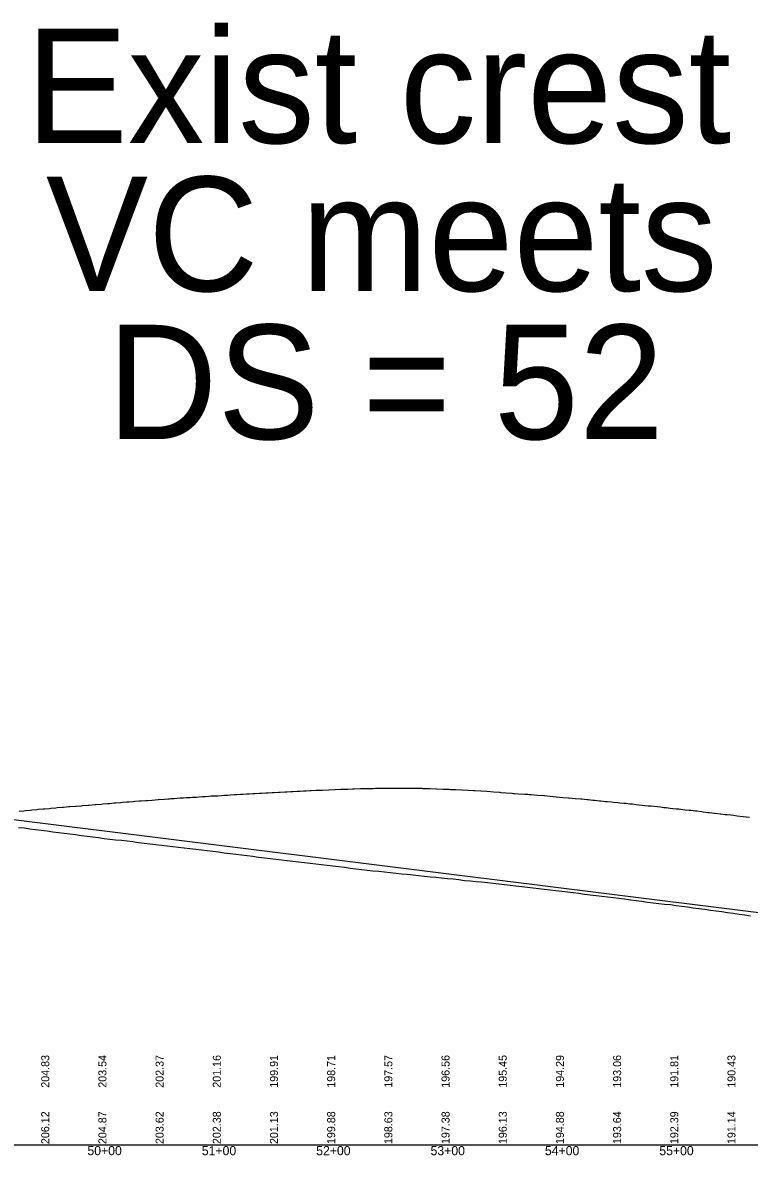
# Model space of a CAD drawing. Extents: x 1876258 to 1932803, y 754739 to 837911.
# Drawn here: x 1881589 to 1882224, y 820541 to 821531 of the extents above; entities that cross this region are included whole.
import ezdxf

# ---------------------------------------------------------------- set-up
doc = ezdxf.new("R2010")
doc.units = 0
for name, color, linetype in [('RD_DDB_Profile_EX', 7, 'Continuous'), ('RD_DDB_Profile_PR', 7, 'Continuous'), ('RD_DDB_StaTX', 7, 'Continuous'), ('RD_DDB_StripGrade', 7, 'Continuous'), ('RD_GPK_Profile_Cell', 7, 'Continuous'), ('RD_Sketch1', 7, 'Continuous')]:
    doc.layers.add(name, color=color, linetype=linetype)

msp = doc.modelspace()

# ---------------------------------------------------------------- linework, layer by layer
at = {"layer": 'RD_DDB_Profile_EX'}
for points in [[(1881585.15, 820827.81), (1881590.15, 820827.26), (1881595.15, 820826.62), (1881600.15, 820825.84), (1881605.15, 820825.25), (1881610.15, 820824.65), (1881615.15, 820824.01), (1881620.15, 820823.34), (1881625.15, 820822.71), (1881630.15, 820822.08), (1881635.15, 820821.43), (1881640.15, 820820.79), (1881645.15, 820820.14), (1881650.15, 820819.48), (1881655.15, 820818.8), (1881660.15, 820818.13), (1881665.15, 820817.58), (1881670.15, 820817.02), (1881675.15, 820816.46), (1881680.15, 820815.88), (1881685.15, 820815.29), (1881690.15, 820814.66), (1881695.15, 820814.02), (1881700.15, 820813.44), (1881705.15, 820812.91), (1881710.15, 820812.32), (1881715.15, 820811.69), (1881720.15, 820811.08), (1881725.15, 820810.5), (1881730.15, 820809.92), (1881735.15, 820809.36), (1881740.15, 820808.8), (1881745.15, 820808.2), (1881750.15, 820807.57), (1881755.15, 820806.94), (1881760.15, 820806.31), (1881765.15, 820805.67), (1881770.15, 820805.08), (1881775.15, 820804.48), (1881780.15, 820803.83), (1881785.15, 820803.17), (1881790.15, 820802.49), (1881795.15, 820801.79), (1881800.15, 820801.21), (1881805.15, 820800.67), (1881810.15, 820800.05), (1881815.15, 820799.36), (1881820.15, 820798.74), (1881825.15, 820798.17), (1881830.15, 820797.59), (1881835.15, 820797.03), (1881840.15, 820796.44), (1881845.15, 820795.84), (1881850.15, 820795.24), (1881855.15, 820794.63), (1881860.15, 820794.02), (1881865.15, 820793.45), (1881870.15, 820792.87), (1881875.15, 820792.24), (1881880.15, 820791.6), (1881885.15, 820790.99), (1881890.15, 820790.37)], [(1881890.15, 820790.37), (1881895.15, 820789.85), (1881900.15, 820789.36), (1881905.15, 820788.84), (1881910.15, 820788.29), (1881915.15, 820787.78), (1881920.15, 820787.3), (1881925.15, 820786.8), (1881930.15, 820786.29), (1881935.15, 820785.76), (1881940.15, 820785.22), (1881945.15, 820784.68), (1881950.15, 820784.21), (1881955.15, 820783.73), (1881960.15, 820783.22), (1881965.15, 820782.7), (1881970.15, 820782.09), (1881975.15, 820781.47), (1881980.15, 820780.93), (1881985.15, 820780.47), (1881990.15, 820780.03), (1881995.15, 820779.48), (1882000.15, 820778.87), (1882005.15, 820778.28), (1882010.15, 820777.71), (1882015.15, 820777.13), (1882020.15, 820776.56), (1882025.15, 820776), (1882030.15, 820775.46), (1882035.15, 820774.91), (1882040.15, 820774.33), (1882045.15, 820773.74), (1882050.15, 820773.13), (1882055.15, 820772.51), (1882060.15, 820771.92), (1882065.15, 820771.36), (1882070.15, 820770.78), (1882075.15, 820770.14), (1882080.15, 820769.51), (1882085.15, 820768.88), (1882090.15, 820768.26), (1882095.15, 820767.64), (1882100.15, 820767.04), (1882105.15, 820766.42), (1882110.15, 820765.8), (1882115.15, 820765.17), (1882120.15, 820764.53), (1882125.15, 820763.88), (1882130.15, 820763.19), (1882135.15, 820762.53), (1882140.15, 820761.9), (1882145.15, 820761.29), (1882150.15, 820760.77), (1882155.15, 820760.22), (1882160.15, 820759.55), (1882165.15, 820758.87), (1882170.15, 820758.17), (1882175.15, 820757.49), (1882180.15, 820756.81), (1882185.15, 820756.13), (1882190.15, 820755.45), (1882195.15, 820754.76), (1882200.15, 820754.1), (1882205.15, 820753.45), (1882210.15, 820752.74), (1882215.15, 820751.97), (1882220.15, 820751.23), (1882225.15, 820750.53)]]:
    msp.add_lwpolyline(points, dxfattribs=at)
at = {"layer": 'RD_DDB_Profile_PR'}
msp.add_line((1881558.08, 820837.6), (1882275.08, 820748.07), dxfattribs=at)
at = {"layer": 'RD_GPK_Profile_Cell'}
msp.add_line((1878363.08, 820550.13), (1884763.08, 820550.13), dxfattribs=at)
at = {"layer": 'RD_Sketch1'}
msp.add_lwpolyline([(1881585.92, 820842.05), (1881589.88, 820842.39), (1881591.43, 820842.55), (1881595.37, 820842.96), (1881596.96, 820843.1), (1881601.17, 820843.5), (1881602.51, 820843.59), (1881606.81, 820843.9), (1881608, 820844.02), (1881612.38, 820844.43), (1881613.53, 820844.54), (1881617.99, 820844.96), (1881619.06, 820845.06), (1881623.76, 820845.49), (1881624.57, 820845.57), (1881629.16, 820846.01), (1881630.14, 820846.07), (1881634.78, 820846.35), (1881635.65, 820846.41), (1881640.29, 820846.76), (1881641.16, 820846.83), (1881646.05, 820847.24), (1881646.69, 820847.29), (1881652.21, 820847.73), (1881653.12, 820847.8), (1881657.73, 820848.19), (1881658.97, 820848.3), (1881663.25, 820848.66), (1881664.65, 820848.78), (1881668.77, 820849.13), (1881670.15, 820849.25), (1881674.31, 820849.56), (1881676.01, 820849.69), (1881679.82, 820850), (1881681.63, 820850.15), (1881685.34, 820850.47), (1881687.02, 820850.62), (1881690.89, 820850.88), (1881692.52, 820850.99), (1881696.4, 820851.28), (1881698.24, 820851.42), (1881701.92, 820851.69), (1881702.08, 820851.71), (1881707.45, 820852.12), (1881707.55, 820852.13), (1881712.87, 820852.48), (1881712.98, 820852.49), (1881715.94, 820852.68), (1881717.31, 820852.88), (1881718.5, 820852.96), (1881721.39, 820853.15), (1881724.02, 820853.34), (1881726.57, 820853.52), (1881729.57, 820853.68), (1881731.97, 820853.81), (1881735.08, 820854), (1881737.24, 820854.13), (1881740.6, 820854.34), (1881742.79, 820854.48), (1881746.12, 820854.7), (1881748.34, 820854.84), (1881751.64, 820855.07), (1881753.79, 820855.22), (1881757.19, 820855.39), (1881759.43, 820855.5), (1881762.7, 820855.69), (1881765.25, 820855.83), (1881768.21, 820856.03), (1881770.46, 820856.19), (1881773.74, 820856.4), (1881776.12, 820856.55), (1881779.28, 820856.7), (1881781.48, 820856.81), (1881784.78, 820857.04), (1881787.01, 820857.19), (1881790.31, 820857.4), (1881792.19, 820857.52), (1881795.85, 820857.71), (1881797.79, 820857.8), (1881801.38, 820857.96), (1881803.33, 820858.04), (1881806.9, 820858.21), (1881808.55, 820858.29), (1881812.42, 820858.5), (1881813.97, 820858.58), (1881817.94, 820858.8), (1881819.84, 820858.9), (1881823.46, 820859.09), (1881825.03, 820859.17), (1881828.99, 820859.37), (1881831.41, 820859.49), (1881834.52, 820859.63), (1881836.67, 820859.73), (1881840.04, 820859.89), (1881840.98, 820859.94), (1881845.54, 820860.23), (1881845.73, 820860.25), (1881850.9, 820860.45), (1881851.09, 820860.45), (1881856.47, 820860.68), (1881856.62, 820860.69), (1881861.83, 820860.91), (1881862.14, 820860.92), (1881866.93, 820861.12), (1881867.69, 820861.14), (1881872.57, 820861.25), (1881873.21, 820861.26), (1881877.64, 820861.36), (1881878.7, 820861.41), (1881884.23, 820861.66), (1881886.41, 820861.77), (1881886.56, 820861.77), (1881886.7, 820861.78), (1881886.8, 820861.78), (1881889.79, 820861.83), (1881890.24, 820861.84), (1881895.31, 820861.92), (1881897.47, 820861.96), (1881898.26, 820861.97), (1881900.84, 820862), (1881906.37, 820862.05), (1881908.55, 820862.07), (1881911.43, 820862.1), (1881911.65, 820862.1), (1881911.89, 820862.1), (1881917.42, 820862.15), (1881921.36, 820862.18), (1881921.77, 820862.18), (1881922.97, 820862.16), (1881928.49, 820862.09), (1881934.01, 820862.01), (1881937.8, 820861.95), (1881938.73, 820861.92), (1881939.56, 820861.9), (1881945.08, 820861.72), (1881950.27, 820861.56), (1881950.58, 820861.54), (1881950.62, 820861.54), (1881956.14, 820861.31), (1881961.66, 820861.08), (1881963.02, 820861.02), (1881963.26, 820861.01), (1881967.19, 820860.83), (1881972.72, 820860.58), (1881978.24, 820860.32), (1881983, 820860.1), (1881983.15, 820860.09), (1881983.79, 820860.05), (1881989.31, 820859.68), (1881994.54, 820859.33), (1881994.73, 820859.31), (1881994.84, 820859.3), (1882000.37, 820858.89), (1882005.89, 820858.47), (1882005.94, 820858.47), (1882006.62, 820858.42), (1882011.42, 820858.05), (1882016.94, 820857.62), (1882017.86, 820857.55), (1882018.94, 820857.47), (1882022.45, 820857.24), (1882027.98, 820856.86), (1882030.41, 820856.69), (1882031.58, 820856.6), (1882033.51, 820856.45), (1882039.03, 820856.03), (1882044.56, 820855.6), (1882045.05, 820855.56), (1882050.11, 820855.06), (1882055.39, 820854.53), (1882055.51, 820854.51), (1882055.61, 820854.5), (1882055.61, 820854.5), (1882061.14, 820854.03), (1882066.2, 820853.6), (1882066.66, 820853.56), (1882071.79, 820853.12), (1882072.18, 820853.09), (1882076.86, 820852.7), (1882077.73, 820852.61), (1882082.26, 820852.13), (1882083.26, 820852.02), (1882087.39, 820851.55), (1882088.76, 820851.43), (1882093.04, 820851.04), (1882094.28, 820850.93), (1882098.35, 820850.55), (1882099.81, 820850.4), (1882103.59, 820850.04), (1882105.33, 820849.88), (1882109.07, 820849.55), (1882110.86, 820849.37), (1882114.58, 820849.01), (1882116.39, 820848.83), (1882119.69, 820848.49), (1882121.93, 820848.23), (1882125.1, 820847.86), (1882127.45, 820847.59), (1882130.4, 820847.25), (1882132.94, 820847.02), (1882135.85, 820846.75), (1882138.48, 820846.5), (1882141.06, 820846.25), (1882144.02, 820845.9), (1882146.43, 820845.61), (1882149.54, 820845.26), (1882151.59, 820845.03), (1882155.06, 820844.66), (1882157.18, 820844.43), (1882160.58, 820844.08), (1882162.47, 820843.88), (1882166.12, 820843.45), (1882167.78, 820843.26), (1882171.62, 820842.87), (1882173.08, 820842.72), (1882177.16, 820842.25), (1882178.38, 820842.11), (1882182.69, 820841.57), (1882183.9, 820841.43), (1882188.21, 820840.93), (1882189.04, 820840.84), (1882193.73, 820840.31), (1882194.23, 820840.26), (1882198.68, 820839.71), (1882199.27, 820839.63), (1882202.94, 820839.17), (1882204.77, 820838.97), (1882207.94, 820838.62), (1882210.32, 820838.32), (1882213.69, 820837.88), (1882215.83, 820837.62), (1882218.75, 820837.27), (1882221.33, 820837), (1882224.33, 820836.68)], dxfattribs=at)
msp.add_lwpolyline([(1881585.92, 820842.05), (1881589.88, 820842.39), (1881591.43, 820842.55), (1881595.37, 820842.96), (1881596.96, 820843.1), (1881601.17, 820843.5), (1881602.51, 820843.59), (1881606.81, 820843.9), (1881608, 820844.02), (1881612.38, 820844.43), (1881613.53, 820844.54), (1881617.99, 820844.96), (1881619.06, 820845.06), (1881623.76, 820845.49), (1881624.57, 820845.57), (1881629.16, 820846.01), (1881630.14, 820846.07), (1881634.78, 820846.35), (1881635.65, 820846.41), (1881640.29, 820846.76), (1881641.16, 820846.83), (1881646.05, 820847.24), (1881646.69, 820847.29), (1881652.21, 820847.73), (1881653.12, 820847.8), (1881657.73, 820848.19), (1881658.97, 820848.3), (1881663.25, 820848.66), (1881664.65, 820848.78), (1881668.77, 820849.13), (1881670.15, 820849.25), (1881674.31, 820849.56), (1881676.01, 820849.69), (1881679.82, 820850), (1881681.63, 820850.15), (1881685.34, 820850.47), (1881687.02, 820850.62), (1881690.89, 820850.88), (1881692.52, 820850.99), (1881696.4, 820851.28), (1881698.24, 820851.42), (1881701.92, 820851.69), (1881702.08, 820851.71), (1881707.45, 820852.12), (1881707.55, 820852.13), (1881712.87, 820852.48), (1881712.98, 820852.49), (1881715.94, 820852.68), (1881717.31, 820852.88), (1881718.5, 820852.96), (1881721.39, 820853.15), (1881724.02, 820853.34), (1881726.57, 820853.52), (1881729.57, 820853.68), (1881731.97, 820853.81), (1881735.08, 820854), (1881737.24, 820854.13), (1881740.6, 820854.34), (1881742.79, 820854.48), (1881746.12, 820854.7), (1881748.34, 820854.84), (1881751.64, 820855.07), (1881753.79, 820855.22), (1881757.19, 820855.39), (1881759.43, 820855.5), (1881762.7, 820855.69), (1881765.25, 820855.83), (1881768.21, 820856.03), (1881770.46, 820856.19), (1881773.74, 820856.4), (1881776.12, 820856.55), (1881779.28, 820856.7), (1881781.48, 820856.81), (1881784.78, 820857.04), (1881787.01, 820857.19), (1881790.31, 820857.4), (1881792.19, 820857.52), (1881795.85, 820857.71), (1881797.79, 820857.8), (1881801.38, 820857.96), (1881803.33, 820858.04), (1881806.9, 820858.21), (1881808.55, 820858.29), (1881812.42, 820858.5), (1881813.97, 820858.58), (1881817.94, 820858.8), (1881819.84, 820858.9), (1881823.46, 820859.09), (1881825.03, 820859.17), (1881828.99, 820859.37), (1881831.41, 820859.49), (1881834.52, 820859.63), (1881836.67, 820859.73), (1881840.04, 820859.89), (1881840.98, 820859.94), (1881845.54, 820860.23), (1881845.73, 820860.25), (1881850.9, 820860.45), (1881851.09, 820860.45), (1881856.47, 820860.68), (1881856.62, 820860.69), (1881861.83, 820860.91), (1881862.14, 820860.92), (1881866.93, 820861.12), (1881867.69, 820861.14), (1881872.57, 820861.25), (1881873.21, 820861.26), (1881877.64, 820861.36), (1881878.7, 820861.41), (1881884.23, 820861.66), (1881886.41, 820861.77), (1881886.56, 820861.77), (1881886.7, 820861.78), (1881886.8, 820861.78), (1881889.79, 820861.83), (1881890.24, 820861.84), (1881895.31, 820861.92), (1881897.47, 820861.96), (1881898.26, 820861.97), (1881900.84, 820862), (1881906.37, 820862.05), (1881908.55, 820862.07), (1881911.43, 820862.1), (1881911.65, 820862.1), (1881911.89, 820862.1), (1881917.42, 820862.15), (1881921.36, 820862.18), (1881921.77, 820862.18), (1881922.97, 820862.16), (1881928.49, 820862.09), (1881934.01, 820862.01), (1881937.8, 820861.95), (1881938.73, 820861.92), (1881939.56, 820861.9), (1881945.08, 820861.72), (1881950.27, 820861.56), (1881950.58, 820861.54), (1881950.62, 820861.54), (1881956.14, 820861.31), (1881961.66, 820861.08), (1881963.02, 820861.02), (1881963.26, 820861.01), (1881967.19, 820860.83), (1881972.72, 820860.58), (1881978.24, 820860.32), (1881983, 820860.1), (1881983.15, 820860.09), (1881983.79, 820860.05), (1881989.31, 820859.68), (1881994.54, 820859.33), (1881994.73, 820859.31), (1881994.84, 820859.3), (1882000.37, 820858.89), (1882005.89, 820858.47), (1882005.94, 820858.47), (1882006.62, 820858.42), (1882011.42, 820858.05), (1882016.94, 820857.62), (1882017.86, 820857.55), (1882018.94, 820857.47), (1882022.45, 820857.24), (1882027.98, 820856.86), (1882030.41, 820856.69), (1882031.58, 820856.6), (1882033.51, 820856.45), (1882039.03, 820856.03), (1882044.56, 820855.6), (1882045.05, 820855.56), (1882050.11, 820855.06), (1882055.39, 820854.53), (1882055.51, 820854.51), (1882055.61, 820854.5), (1882055.61, 820854.5), (1882061.14, 820854.03), (1882066.2, 820853.6), (1882066.66, 820853.56), (1882071.79, 820853.12), (1882072.18, 820853.09), (1882076.86, 820852.7), (1882077.73, 820852.61), (1882082.26, 820852.13), (1882083.26, 820852.02), (1882087.39, 820851.55), (1882088.76, 820851.43), (1882093.04, 820851.04), (1882094.28, 820850.93), (1882098.35, 820850.55), (1882099.81, 820850.4), (1882103.59, 820850.04), (1882105.33, 820849.88), (1882109.07, 820849.55), (1882110.86, 820849.37), (1882114.58, 820849.01), (1882116.39, 820848.83), (1882119.69, 820848.49), (1882121.93, 820848.23), (1882125.1, 820847.86), (1882127.45, 820847.59), (1882130.4, 820847.25), (1882132.94, 820847.02), (1882135.85, 820846.75), (1882138.48, 820846.5), (1882141.06, 820846.25), (1882144.02, 820845.9), (1882146.43, 820845.61), (1882149.54, 820845.26), (1882151.59, 820845.03), (1882155.06, 820844.66), (1882157.18, 820844.43), (1882160.58, 820844.08), (1882162.47, 820843.88), (1882166.12, 820843.45), (1882167.78, 820843.26), (1882171.62, 820842.87), (1882173.08, 820842.72), (1882177.16, 820842.25), (1882178.38, 820842.11), (1882182.69, 820841.57), (1882183.9, 820841.43), (1882188.21, 820840.93), (1882189.04, 820840.84), (1882193.73, 820840.31), (1882194.23, 820840.26), (1882198.68, 820839.71), (1882199.27, 820839.63), (1882202.94, 820839.17), (1882204.77, 820838.97), (1882207.94, 820838.62), (1882210.32, 820838.32), (1882213.69, 820837.88), (1882215.83, 820837.62), (1882218.75, 820837.27), (1882221.33, 820837), (1882224.33, 820836.68)], dxfattribs=at)
msp.add_lwpolyline([(1881585.92, 820842.05), (1881589.88, 820842.39), (1881591.43, 820842.55), (1881595.37, 820842.96), (1881596.96, 820843.1), (1881601.17, 820843.5), (1881602.51, 820843.59), (1881606.81, 820843.9), (1881608, 820844.02), (1881612.38, 820844.43), (1881613.53, 820844.54), (1881617.99, 820844.96), (1881619.06, 820845.06), (1881623.76, 820845.49), (1881624.57, 820845.57), (1881629.16, 820846.01), (1881630.14, 820846.07), (1881634.78, 820846.35), (1881635.65, 820846.41), (1881640.29, 820846.76), (1881641.16, 820846.83), (1881646.05, 820847.24), (1881646.69, 820847.29), (1881652.21, 820847.73), (1881653.12, 820847.8), (1881657.73, 820848.19), (1881658.97, 820848.3), (1881663.25, 820848.66), (1881664.65, 820848.78), (1881668.77, 820849.13), (1881670.15, 820849.25), (1881674.31, 820849.56), (1881676.01, 820849.69), (1881679.82, 820850), (1881681.63, 820850.15), (1881685.34, 820850.47), (1881687.02, 820850.62), (1881690.89, 820850.88), (1881692.52, 820850.99), (1881696.4, 820851.28), (1881698.24, 820851.42), (1881701.92, 820851.69), (1881702.08, 820851.71), (1881707.45, 820852.12), (1881707.55, 820852.13), (1881712.87, 820852.48), (1881712.98, 820852.49), (1881715.94, 820852.68), (1881717.31, 820852.88), (1881718.5, 820852.96), (1881721.39, 820853.15), (1881724.02, 820853.34), (1881726.57, 820853.52), (1881729.57, 820853.68), (1881731.97, 820853.81), (1881735.08, 820854), (1881737.24, 820854.13), (1881740.6, 820854.34), (1881742.79, 820854.48), (1881746.12, 820854.7), (1881748.34, 820854.84), (1881751.64, 820855.07), (1881753.79, 820855.22), (1881757.19, 820855.39), (1881759.43, 820855.5), (1881762.7, 820855.69), (1881765.25, 820855.83), (1881768.21, 820856.03), (1881770.46, 820856.19), (1881773.74, 820856.4), (1881776.12, 820856.55), (1881779.28, 820856.7), (1881781.48, 820856.81), (1881784.78, 820857.04), (1881787.01, 820857.19), (1881790.31, 820857.4), (1881792.19, 820857.52), (1881795.85, 820857.71), (1881797.79, 820857.8), (1881801.38, 820857.96), (1881803.33, 820858.04), (1881806.9, 820858.21), (1881808.55, 820858.29), (1881812.42, 820858.5), (1881813.97, 820858.58), (1881817.94, 820858.8), (1881819.84, 820858.9), (1881823.46, 820859.09), (1881825.03, 820859.17), (1881828.99, 820859.37), (1881831.41, 820859.49), (1881834.52, 820859.63), (1881836.67, 820859.73), (1881840.04, 820859.89), (1881840.98, 820859.94), (1881845.54, 820860.23), (1881845.73, 820860.25), (1881850.9, 820860.45), (1881851.09, 820860.45), (1881856.47, 820860.68), (1881856.62, 820860.69), (1881861.83, 820860.91), (1881862.14, 820860.92), (1881866.93, 820861.12), (1881867.69, 820861.14), (1881872.57, 820861.25), (1881873.21, 820861.26), (1881877.64, 820861.36), (1881878.7, 820861.41), (1881884.23, 820861.66), (1881886.41, 820861.77), (1881886.56, 820861.77), (1881886.7, 820861.78), (1881886.8, 820861.78), (1881889.79, 820861.83), (1881890.24, 820861.84), (1881895.31, 820861.92), (1881897.47, 820861.96), (1881898.26, 820861.97), (1881900.84, 820862), (1881906.37, 820862.05), (1881908.55, 820862.07), (1881911.43, 820862.1), (1881911.65, 820862.1), (1881911.89, 820862.1), (1881917.42, 820862.15), (1881921.36, 820862.18), (1881921.77, 820862.18), (1881922.97, 820862.16), (1881928.49, 820862.09), (1881934.01, 820862.01), (1881937.8, 820861.95), (1881938.73, 820861.92), (1881939.56, 820861.9), (1881945.08, 820861.72), (1881950.27, 820861.56), (1881950.58, 820861.54), (1881950.62, 820861.54), (1881956.14, 820861.31), (1881961.66, 820861.08), (1881963.02, 820861.02), (1881963.26, 820861.01), (1881967.19, 820860.83), (1881972.72, 820860.58), (1881978.24, 820860.32), (1881983, 820860.1), (1881983.15, 820860.09), (1881983.79, 820860.05), (1881989.31, 820859.68), (1881994.54, 820859.33), (1881994.73, 820859.31), (1881994.84, 820859.3), (1882000.37, 820858.89), (1882005.89, 820858.47), (1882005.94, 820858.47), (1882006.62, 820858.42), (1882011.42, 820858.05), (1882016.94, 820857.62), (1882017.86, 820857.55), (1882018.94, 820857.47), (1882022.45, 820857.24), (1882027.98, 820856.86), (1882030.41, 820856.69), (1882031.58, 820856.6), (1882033.51, 820856.45), (1882039.03, 820856.03), (1882044.56, 820855.6), (1882045.05, 820855.56), (1882050.11, 820855.06), (1882055.39, 820854.53), (1882055.51, 820854.51), (1882055.61, 820854.5), (1882055.61, 820854.5), (1882061.14, 820854.03), (1882066.2, 820853.6), (1882066.66, 820853.56), (1882071.79, 820853.12), (1882072.18, 820853.09), (1882076.86, 820852.7), (1882077.73, 820852.61), (1882082.26, 820852.13), (1882083.26, 820852.02), (1882087.39, 820851.55), (1882088.76, 820851.43), (1882093.04, 820851.04), (1882094.28, 820850.93), (1882098.35, 820850.55), (1882099.81, 820850.4), (1882103.59, 820850.04), (1882105.33, 820849.88), (1882109.07, 820849.55), (1882110.86, 820849.37), (1882114.58, 820849.01), (1882116.39, 820848.83), (1882119.69, 820848.49), (1882121.93, 820848.23), (1882125.1, 820847.86), (1882127.45, 820847.59), (1882130.4, 820847.25), (1882132.94, 820847.02), (1882135.85, 820846.75), (1882138.48, 820846.5), (1882141.06, 820846.25), (1882144.02, 820845.9), (1882146.43, 820845.61), (1882149.54, 820845.26), (1882151.59, 820845.03), (1882155.06, 820844.66), (1882157.18, 820844.43), (1882160.58, 820844.08), (1882162.47, 820843.88), (1882166.12, 820843.45), (1882167.78, 820843.26), (1882171.62, 820842.87), (1882173.08, 820842.72), (1882177.16, 820842.25), (1882178.38, 820842.11), (1882182.69, 820841.57), (1882183.9, 820841.43), (1882188.21, 820840.93), (1882189.04, 820840.84), (1882193.73, 820840.31), (1882194.23, 820840.26), (1882198.68, 820839.71), (1882199.27, 820839.63), (1882202.94, 820839.17), (1882204.77, 820838.97), (1882207.94, 820838.62), (1882210.32, 820838.32), (1882213.69, 820837.88), (1882215.83, 820837.62), (1882218.75, 820837.27), (1882221.33, 820837), (1882224.33, 820836.68)], dxfattribs=at)

# ---------------------------------------------------------------- texts
at = {"layer": 'RD_DDB_StaTX'}
for s, p in [('50+00', (1881645.49, 820541.13)), ('51+00', (1881745.49, 820541.13)), ('52+00', (1881845.49, 820541.13)), ('53+00', (1881945.49, 820541.13)), ('54+00', (1882045.49, 820541.13)), ('55+00', (1882145.49, 820541.13))]:
    msp.add_text(s, height=8, dxfattribs=at).set_placement(p)
at = {"layer": 'RD_DDB_StripGrade'}
for s, p in [('204.83', (1881612.08, 820600.13)), ('203.54', (1881662.08, 820600.13)), ('202.37', (1881712.08, 820600.13)), ('201.16', (1881762.08, 820600.13)), ('199.91', (1881812.08, 820600.13)), ('198.71', (1881862.08, 820600.13)), ('197.57', (1881912.08, 820600.13)), ('196.56', (1881962.08, 820600.13)), ('195.45', (1882012.08, 820600.13)), ('194.29', (1882062.08, 820600.13)), ('193.06', (1882112.08, 820600.13)), ('191.81', (1882162.08, 820600.13)), ('190.43', (1882212.08, 820600.13)), ('206.12', (1881612.08, 820550.88)), ('204.87', (1881662.08, 820550.88)), ('203.62', (1881712.08, 820550.88)), ('202.38', (1881762.08, 820550.88)), ('201.13', (1881812.08, 820550.88)), ('199.88', (1881862.08, 820550.88)), ('198.63', (1881912.08, 820550.88)), ('197.38', (1881962.08, 820550.88)), ('196.13', (1882012.08, 820550.88)), ('194.88', (1882062.08, 820550.88)), ('193.64', (1882112.08, 820550.88)), ('192.39', (1882162.08, 820550.88)), ('191.14', (1882212.08, 820550.88))]:
    msp.add_text(s, height=7, rotation=90, dxfattribs=at).set_placement(p)
at = {"layer": 'RD_Sketch1'}
for s, p in [('Exist crest', (1881591.61, 821426.1)), ('Exist crest', (1881591.61, 821426.1)), ('Exist crest', (1881591.61, 821426.1)), ('VC meets', (1881609.25, 821296.68)), ('VC meets', (1881609.25, 821296.68)), ('VC meets', (1881609.25, 821296.68)), ('DS = 52', (1881662.65, 821167.26)), ('DS = 52', (1881662.65, 821167.26)), ('DS = 52', (1881662.65, 821167.26))]:
    msp.add_text(s, height=100, dxfattribs=at).set_placement(p)

doc.saveas('drawing.dxf')
